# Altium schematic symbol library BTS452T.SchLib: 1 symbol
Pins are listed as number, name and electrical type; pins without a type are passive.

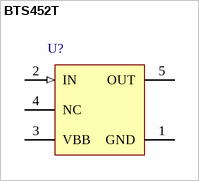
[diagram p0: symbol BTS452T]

## BTS452T
designator U?
Smart High-Side Power Switch, 1 Channel, 1.3 A Load Current, -40 to 150 degC, PG-TO252-5-11, Reel, Green; Manufacturer: Infineon; PartNumber: BTS452T; Channels: 1; Green: TRUE; Group: Automotive Qualified; Load Current (typ): 1.3 A; Ptot (max): 41.6 W; Recommended Operating Voltage Max.: 52 V; Recommended Operating Voltage Min.: 6 V; RON @ 25degreesC: 200 mOhm; RON(max) @ 150degreesC: 380 mOhm; toff (max): 200 us; ton (max): 180 us
footprint INF-PG-TO252-5-11_N (DPAK, 5-Leads, Body 6.5x6.12mm, Pitch 1.14mm, IPC Medium Density)
footprint INF-PG-TO252-5-11_L (DPAK, 5-Leads, Body 6.5x6.12mm, Pitch 1.14mm, IPC High Density)
footprint INF-PG-TO252-5-11_M (DPAK, 5-Leads, Body 6.5x6.12mm, Pitch 1.14mm, IPC Low Density)
pins: 1 GND (power) "Logic ground.", 2 IN (in) "Input, activates the power switch in case of logical high signal.", 3 VBB (power) "Positive power supply voltage.", 4 NC "Not connected.", 5 OUT (power) "Output to the load."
